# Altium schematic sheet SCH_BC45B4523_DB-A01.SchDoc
size A4
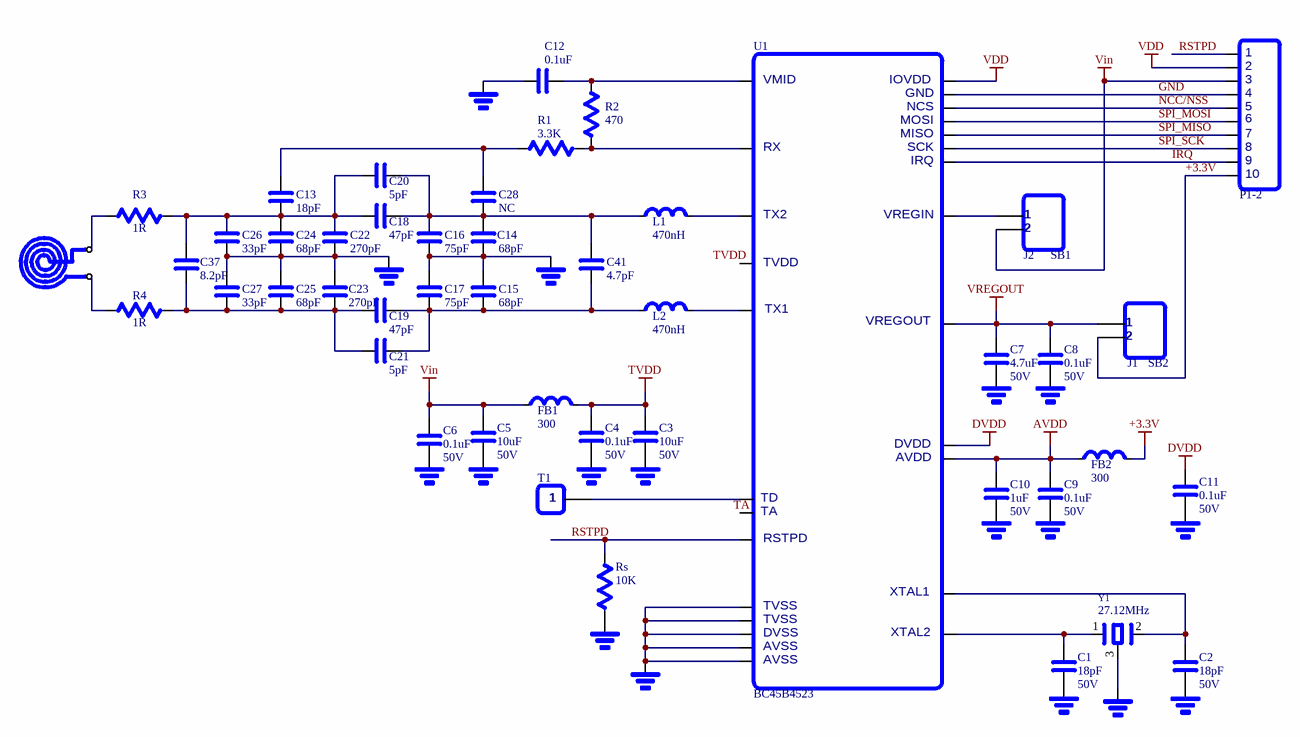
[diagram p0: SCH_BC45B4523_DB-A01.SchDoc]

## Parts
(Parts that share a designator on the sheet are numbered #1, #2 ... from top to bottom, then left to right.)
*#1  GND(1)  (value not drawn)
*#2  GND(1)  (value not drawn)
*#3  GND(1)  (value not drawn)
*#4  GND(1)  (value not drawn)
*#5  GND(1)  (value not drawn)
*#6  GND(1)  (value not drawn)
*#7  GND(1)  (value not drawn)
*#8  GND(1)  (value not drawn)
*#9  GND(1)  (value not drawn)
*#10  GND(1)  (value not drawn)
*#11  GND(1)  (value not drawn)
*#12  GND(1)  (value not drawn)
*#13  GND(1)  (value not drawn)
*#14  GND(1)  (value not drawn)
*#15  GND(1)  (value not drawn)
*#16  GND(1)  (value not drawn)
*#17  GND(1)  (value not drawn)
*?  Induction(2)  (value not drawn)
C1  18pF  value 50V
C2  18pF  value 50V
C3  10uF  value 50V
C4  0.1uF  value 50V
C5  10uF  value 50V
C6  0.1uF  value 50V
C7  4.7uF  value 50V
C8  0.1uF  value 50V
C9  0.1uF  value 50V
C10  1uF  value 50V
C11  0.1uF  value 50V
C12  0.1uF
C13  18pF
C14  68pF
C15  68pF
C16  75pF
C17  75pF
C18  47pF
C19  47pF
C20  5pF
C21  5pF
C22  270pF
C23  270pF
C24  68pF
C25  68pF
C26  33pF
C27  33pF
C28  NC
C37  8.2pF
C41  4.7pF
FB1  300
FB2  300
J1  SB2
J2  SB1
L1  470nH
L2  470nH
P1-2  CON*10  (value not drawn)
R1  3.3K
R2  470
R3  1R
R4  1R
Rs  10K
T1  CON1  (value not drawn)
U1  BC45B4523
Y1  27.12MHz  [XTAL-49US]

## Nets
+3.3V: FB2.2 J1.1(CON?) P1-2.18
AVDD: C9.1 C10.1 FB2.1 U1.6(PDN)
DVDD: C11.1 U1.2(SPICSN)
TVDD: C3.1 C4.1 FB1.2
VDD: P1-2.16 U1.10(EXINT)
Vin: C5.1 C6.1 FB1.1 J2.1(CON?) P1-2.17
VREGOUT: C7.1 C8.1 J1.1(CON?) U1.2(SPICSN)
GND: P1-2.16 U1.9(STATE)
IRQ: P1-2.17 U1.10(EXINT)
NCC/NSS: P1-2.17 U1.10(EXINT)
RSTPD: P1-2.15 Rs.2 U1.6(PDN)
SPI_MISO: P1-2.16 U1.9(STATE)
SPI_MOSI: P1-2.17 U1.8(WAKEUP)
SPI_SCK: P1-2.17 U1.9(STATE)
Net*#1_?1: *#1.?1 C12.2
Net*#2_?1: *#2.?1 C22.2 C23.1 C24.2 C25.1 C26.2 C27.1
Net*#3_?1: *#3.?1 C14.2 C15.1 C16.2 C17.1
Net*#7_?1: *#7.?1 C5.2
Net*#8_?1: *#8.?1 C4.2
Net*#9_?1: *#9.?1 C3.2
Net*#12_?1: *#12.?1 C11.2
Net*#13_?1: *#13.?1 Rs.1
Net*#14_?1: *#14.?1 U1.6(PDN)
Net*#15_?1: *#15.?1 C1.2
Net*#16_?1: *#16.?1 Y1.3(OSC2)
Net*#17_?1: *#17.?1 C2.2
NetC1_1: C1.1 U1.6(PDN) Y1.1(OSC1)
NetC2_1: C2.1 U1.6(PDN) Y1.2(OSC2)
NetC12_1: C12.1 R2.2 U1.6(PDN)
NetC13_1: C13.1 C28.1 R1.1
NetC13_2: C13.2 C18.2 C20.2 C22.1 C24.1 C26.1 C37.1 R3.2
NetC14_1: C14.1 C16.1 C18.1 C20.1 C28.2 C41.1 L1.1
NetC15_2: C15.2 C17.2 C19.1 C21.1 C41.2 L2.1
NetC19_2: C19.2 C21.2 C23.2 C25.2 C27.2 C37.2 R4.2
NetJ2_1: J2.1(CON?) U1.6(PDN)
NetL1_2: L1.2 U1.2(SPICSN)
NetL2_2: L2.2 U1.6(PDN)
NetR1_2: R1.2 R2.1 U1.1(VDD)
NetT1_1: T1.1(CON?) U1.1(VDD)

Not connected (* = marked no-connect by the designer): *#4 ?1; *#5 ?1; *#6 ?1; *#10 ?1; *#11 ?1; C6 2; C7 2; C8 2; C9 2; C10 2; R3 1; R4 1

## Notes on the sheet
- Labels drawn without touching a wire or pin: TA, TVDD

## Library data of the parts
*#1-*#17 = GND(1): GND
C1-C28 C37 C41 = Cap(1): Capacitor
FB1 FB2 L1 L2 = Inductor (1)_2: Inductor; Code_IEC: 1005
J1 J2 = CON2
R1-R4 Rs = Resistor(1): Resisitor
U1 = BCB4523: IC
Y1 = Xtal(2)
